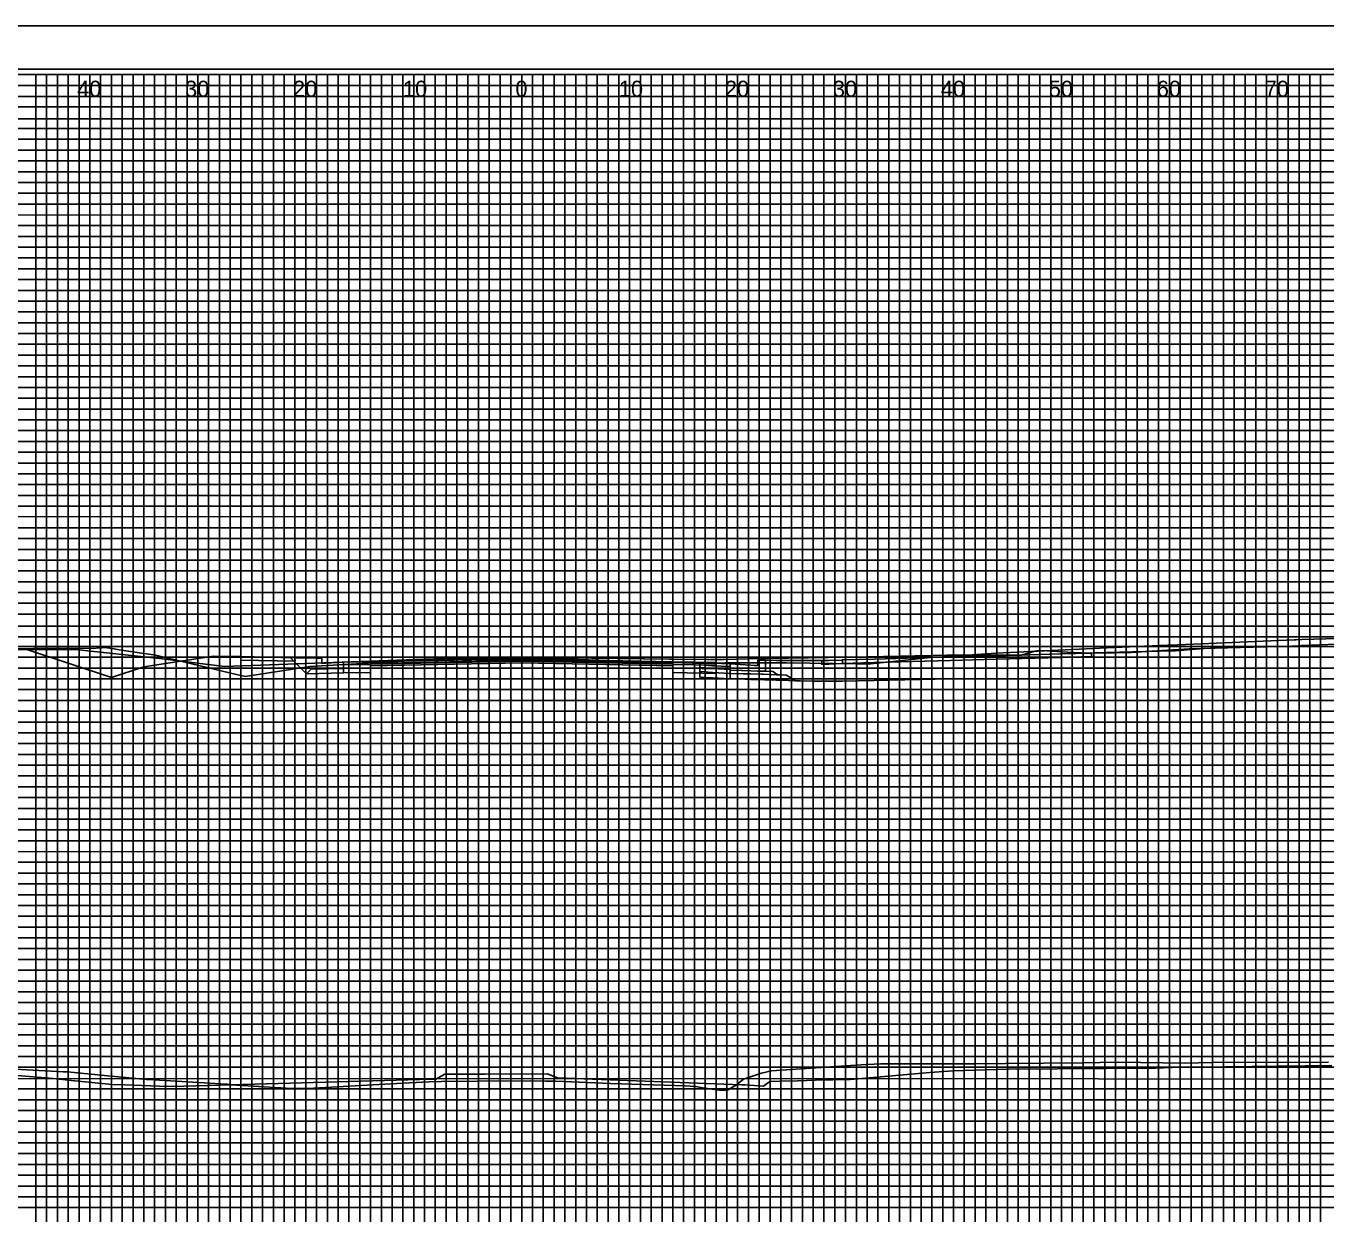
# Model space of a CAD drawing. Extents: x -13 to 760, y -5 to 1491.
# Drawn here: x 114.1 to 234.5, y 104.5 to 214.5 of the extents above; entities that cross this region are included whole.
import ezdxf

# ---------------------------------------------------------------- set-up
doc = ezdxf.new("R2010")
doc.units = 0
for name, color, linetype in [('Exist XS Ground Line', 7, 'Continuous'), ('Prop CMT Concrete Structures', 7, 'Continuous'), ('Prop CMT Pvmt Course 1', 7, 'Continuous'), ('Prop CMT Pvmt Course 2', 7, 'Continuous'), ('Prop CMT Pvmt Course 3', 7, 'Continuous'), ('Prop CMT Pvmt Course 4', 7, 'Continuous'), ('Prop CMT Subgrade Earthwork', 7, 'Continuous'), ('Prop Conc 4in Sidewalk', 7, 'Continuous'), ('Prop Conc Curb and Gutter', 7, 'Continuous'), ('Prop Conc Island Cover', 7, 'Continuous'), ('Prop Corridor Mesh Bottom', 7, 'Continuous'), ('Prop XS Finish Grade', 7, 'Continuous'), ('Prop XS Offset Labels', 7, 'Continuous'), ('Scratch_Level_9', 7, 'Continuous'), ('Sheet Cross Section CELL', 7, 'Continuous'), ('Sheet Cross Section Grid Major CELL', 7, 'Continuous'), ('Sheet Cross Section Grid Middle CELL', 7, 'Continuous'), ('Sheet Cross Section Grid Minor 1 CELL', 7, 'Continuous'), ('Sheet Cross Section Grid Minor 2 CELL', 7, 'Continuous'), ('Sheet Cutting Line CELL', 7, 'Continuous'), ('Sheet DOT Grid CELL', 7, 'Continuous'), ('Sheet Plot Border Inside CELL', 7, 'Continuous'), ('Sheet Plot Border Outside CELL', 7, 'Continuous')]:
    doc.layers.add(name, color=color, linetype=linetype)

msp = doc.modelspace()

# ---------------------------------------------------------------- linework, layer by layer
at = {"layer": 'Exist XS Ground Line'}
for points in [[(110.13, 156.74), (117.11, 156.83), (120.08, 156.81), (121.12, 156.87), (121.36, 156.89), (122.11, 156.8), (122.71, 156.7), (124.6, 156.41), (126.1, 156.21), (126.74, 156.03), (133.58, 154.41), (134.4, 154.22), (134.6, 154.24), (140.39, 155.14), (145.24, 155.43), (152.31, 155.83), (154.97, 155.85), (159.26, 155.88), (162.07, 155.87), (163.31, 155.86), (175.86, 155.44), (176.49, 155.43), (178.86, 155.47), (181.55, 155.48), (183.55, 155.48), (183.67, 155.48), (184.54, 155.48), (191.02, 155.4), (191.7, 155.4), (192.33, 155.38), (197.88, 155.99), (199.1, 156.05), (203.92, 156.37), (205.24, 156.43), (209.69, 156.66), (214.87, 156.9), (219.81, 157.11), (220.77, 157.16), (223.65, 157.28), (231.56, 157.62), (231.71, 157.63), (232.26, 157.65), (236.71, 157.76)], [(110.19, 156.72), (118.68, 156.73), (126.74, 155.85), (132.46, 155.16), (141.67, 155.47), (156.96, 156.05), (173.65, 155.83), (177.15, 155.78), (178.75, 155.79), (181.05, 155.84), (192.07, 156.04), (199.39, 156.18), (200.15, 156.19), (202.22, 156.22), (204.83, 156.19), (206.27, 156.2), (207.56, 156.56), (207.73, 156.61), (207.8, 156.61), (208.16, 156.62), (210.56, 156.47), (212.44, 156.39), (214.88, 156.41), (216.45, 156.43), (219.81, 156.65), (221.84, 156.78), (231.34, 157.04), (232.12, 157.07), (232.22, 157.08), (237.15, 157.28)], [(102.5, 118.14), (116.61, 116.96), (118.3, 116.77), (122.07, 116.4), (123.23, 116.38), (126.41, 116.24), (127.63, 116.22), (151.66, 116.89), (151.75, 116.89), (151.8, 116.89), (152.03, 116.9), (152.04, 116.9), (152.89, 117.36), (156.61, 117.37), (162.38, 117.41), (162.91, 117.18), (163.31, 117.02), (178.72, 116.45), (180.38, 116.38), (180.67, 116.37), (182.4, 116.26), (182.76, 116.52), (183, 116.69), (183.91, 116.72), (185.57, 116.76), (187.18, 116.8), (190.47, 116.88), (197.82, 117.52), (199.97, 117.68), (205.1, 117.83), (218.7, 117.93), (220.25, 117.98), (235.05, 118.16)], [(109.66, 118), (117.54, 117.59), (117.63, 117.58), (117.71, 117.58), (117.84, 117.58), (117.87, 117.58), (117.92, 117.57), (121.68, 117.21), (125.24, 116.88), (125.26, 116.88), (125.31, 116.88), (125.35, 116.87), (125.4, 116.86), (132.65, 116.44), (132.71, 116.43), (132.82, 116.41), (132.91, 116.4), (133, 116.39), (133.08, 116.39), (138.72, 116.05), (138.8, 116.05), (138.88, 116.04), (138.9, 116.04), (138.97, 116.04), (139.02, 116.03), (139.06, 116.03), (139.1, 116.03), (139.13, 116.03), (139.15, 116.03), (139.17, 116.04), (140.71, 116.08), (148.45, 116.49), (151.41, 116.65), (152.58, 116.7), (155.9, 116.72), (160.81, 116.74), (162.25, 116.73), (163.16, 116.71), (168.23, 116.51), (174.2, 116.31), (175.1, 116.28), (176.1, 116.23), (176.77, 116.1), (178.31, 115.88), (178.66, 115.88), (179.06, 115.88), (179.89, 116.39), (180.54, 116.9), (182.22, 117.45), (183.15, 117.68), (189.56, 118.1), (191.92, 118.25), (192.66, 118.29), (193.28, 118.32), (193.58, 118.33), (194.23, 118.32), (202.03, 118.31), (204.82, 118.37), (211.91, 118.42), (215.26, 118.48), (221.45, 118.4), (223.93, 118.44), (234.73, 118.47)]]:
    msp.add_lwpolyline(points, dxfattribs=at)
at = {"layer": 'Prop CMT Pvmt Course 1'}
for points in [[(143.5, 155.54), (146, 155.59), (146, 155.34), (146, 155.34), (143.5, 155.29), (143.5, 155.29), (143.5, 155.29), (143.5, 155.54), (143.5, 155.54)], [(146, 155.43), (146, 155.43), (146, 155.43), (160, 155.71), (174, 155.43), (174, 155.43), (174, 155.43), (174, 155.59), (174, 155.59), (160, 155.87), (146, 155.59), (146, 155.59), (146, 155.43)], [(178, 155.51), (174, 155.59), (174, 155.34), (174, 155.34), (178, 155.26), (178, 155.26), (178, 155.26), (178, 155.51), (178, 155.51)], [(176.5, 155.54), (176.5, 155.29), (177.68, 155.21), (179.3, 155.13), (179.3, 155.38), (177.68, 155.46), (176.5, 155.54)]]:
    msp.add_lwpolyline(points, dxfattribs=at)
at = {"layer": 'Prop CMT Pvmt Course 2'}
for points in [[(143.5, 155.29), (146, 155.34), (146, 155.01), (146, 155.01), (143.5, 154.96), (143.5, 154.96), (143.5, 154.96), (143.5, 155.29), (143.5, 155.29)], [(146, 155.37), (146, 155.37), (146, 155.37), (160, 155.65), (174, 155.37), (174, 155.37), (174, 155.37), (174, 155.43), (174, 155.43), (160, 155.71), (146, 155.43), (146, 155.43), (146, 155.37)], [(178, 155.26), (174, 155.34), (174, 155.01), (174, 155.01), (178, 154.93), (178, 154.93), (178, 154.93), (178, 155.26), (178, 155.26)], [(176.5, 155.29), (176.5, 155.04), (177.68, 154.96), (179.3, 154.88), (179.3, 155.13), (177.68, 155.21), (176.5, 155.29)]]:
    msp.add_lwpolyline(points, dxfattribs=at)
at = {"layer": 'Prop CMT Pvmt Course 3'}
for points in [[(146, 155.2), (146, 155.2), (146, 155.2), (160, 155.48), (174, 155.2), (174, 155.2), (174, 155.2), (174, 155.37), (174, 155.37), (160, 155.65), (146, 155.37), (146, 155.37), (146, 155.2)], [(143.5, 154.96), (143.5, 154.55), (140.07, 154.48), (140.5, 154.9), (143.5, 154.96)], [(143.5, 154.96), (146, 155.01), (146, 154.59), (146, 154.59), (143.5, 154.55), (143.5, 154.55), (143.5, 154.55), (143.5, 154.96), (143.5, 154.96)], [(178, 154.93), (174, 155.01), (174, 154.59), (174, 154.59), (178, 154.51), (178, 154.51), (178, 154.51), (178, 154.93), (178, 154.93)], [(176.5, 155.04), (176.5, 154.67), (177.68, 154.59), (179.3, 154.5), (179.3, 154.88), (177.68, 154.96), (176.5, 155.04)], [(183.68, 154.39), (183.7, 154.38), (183.64, 154.38), (183.61, 154.38), (182.2, 154.42), (181.21, 154.45), (180.51, 154.47), (179.3, 154.5), (179.3, 154.61), (179.3, 154.79), (180.46, 154.76), (181.21, 154.74), (182.08, 154.72), (183.27, 154.68), (183.33, 154.64), (183.61, 154.43), (183.68, 154.39)]]:
    msp.add_lwpolyline(points, dxfattribs=at)
at = {"layer": 'Prop CMT Pvmt Course 4'}
for points in [[(176.5, 154.67), (176.5, 154.17), (177.68, 154.09), (179.3, 154), (179.3, 154.5), (177.68, 154.59), (176.5, 154.67)], [(183.88, 154.37), (184.51, 154.35), (184.83, 154.15), (185.34, 153.83), (184.09, 153.87), (183.61, 153.88), (182.52, 153.92), (181.21, 153.95), (180.66, 153.97), (179.3, 154), (179.3, 154.19), (179.3, 154.5), (180.59, 154.47), (181.21, 154.45), (182.37, 154.42), (183.61, 154.38), (183.88, 154.37)]]:
    msp.add_lwpolyline(points, dxfattribs=at)
at = {"layer": 'Prop CMT Subgrade Earthwork'}
for points in [[(140.07, 154.48), (138.57, 155.97)], [(143.5, 154.55), (140.07, 154.48)], [(143.5, 154.55), (143.5, 154.55), (146, 154.59)], [(178, 154.51), (178, 154.51), (174, 154.59)], [(185.34, 153.83), (184.09, 153.87), (183.61, 153.88), (182.52, 153.92), (181.21, 153.95), (180.66, 153.97), (179.3, 154)], [(185.34, 153.83), (185.48, 153.82), (185.5, 153.82), (185.79, 153.81), (185.8, 153.81), (186.91, 153.78), (187.07, 153.78), (187.51, 153.77), (187.6, 153.77), (187.78, 153.77), (188.45, 153.77), (188.8, 153.78), (189.7, 153.8)], [(189.7, 153.8), (192.64, 153.86), (199.71, 154), (201.39, 154.04)]]:
    msp.add_lwpolyline(points, dxfattribs=at)
at = {"layer": 'Prop Conc 4in Sidewalk'}
for points in [[(139, 155.96), (139.01, 155.63), (133.98, 155.73), (133.99, 156.06), (139, 155.96)], [(189.7, 155.71), (189.7, 155.41), (189.64, 155.41), (188.45, 155.37), (188.43, 155.37), (187.79, 155.36), (187.81, 155.62), (187.82, 155.7), (188.43, 155.71), (188.45, 155.71), (189.64, 155.74), (189.7, 155.75), (189.7, 155.71)], [(189.7, 155.75), (192.64, 155.83), (199.71, 156.03), (202.84, 156.11), (209.9, 156.31), (212.75, 156.39), (212.8, 156.06), (209.9, 155.98), (202.84, 155.78), (199.71, 155.69), (192.64, 155.5), (189.7, 155.41), (189.7, 155.75)]]:
    msp.add_lwpolyline(points, dxfattribs=at)
at = {"layer": 'Prop Conc Curb and Gutter'}
for points in [[(141.84, 155.44), (143.5, 155.54), (143.5, 154.96), (143.5, 154.96), (141.51, 154.92), (141, 154.91), (141, 155.17), (141, 155.92), (141.12, 155.92), (141.5, 155.92), (141.5, 155.53), (141.5, 155.42), (141.84, 155.44)], [(181.56, 155.24), (181.87, 155.23), (181.87, 155.35), (181.87, 155.73), (182.29, 155.72), (182.57, 155.72), (182.57, 155.24), (182.57, 154.7), (181.85, 154.72), (181.21, 154.74), (180.36, 154.77), (179.3, 154.79), (179.3, 155.01), (179.3, 155.38), (180.23, 155.32), (181.21, 155.26), (181.56, 155.24)]]:
    msp.add_lwpolyline(points, dxfattribs=at)
at = {"layer": 'Prop Conc Island Cover'}
msp.add_lwpolyline([(133.99, 156.06), (133.81, 156.06), (131.49, 156.11), (131.46, 156.1), (125, 155.12)], dxfattribs=at)
at = {"layer": 'Prop Corridor Mesh Bottom'}
for points in [[(122, 154.12), (114.17, 156.72)], [(156.96, 156.05), (146, 155.64), (146, 155.64), (146, 155.39), (146, 155.39), (146, 155.39), (156.96, 155.68), (156.96, 155.68), (160, 155.76), (160, 155.76), (160, 156.01), (156.96, 156.05), (156.96, 156.05)], [(173.65, 155.83), (160, 156.01), (160, 155.76), (160, 155.76), (173.65, 155.58), (173.65, 155.58), (174, 155.57), (174, 155.57), (174, 155.82), (173.65, 155.83), (173.65, 155.83)], [(125, 155.12), (122, 154.12)]]:
    msp.add_lwpolyline(points, dxfattribs=at)
at = {"layer": 'Prop XS Finish Grade'}
for points in [[(212.75, 156.39), (213.03, 156.4), (220.09, 156.6), (220.52, 156.61)], [(220.52, 156.61), (223.22, 156.8), (224.36, 156.88)], [(139, 155.96), (140.35, 155.94), (141, 155.92)], [(176.5, 155.54), (177.68, 155.46), (179.3, 155.38)], [(187.82, 155.7), (187.63, 155.69), (187.6, 155.69), (187.58, 155.69), (187.07, 155.69), (186.87, 155.69), (185.8, 155.7), (185.68, 155.7), (185.5, 155.7), (184.25, 155.71), (183.61, 155.71), (182.57, 155.72)]]:
    msp.add_lwpolyline(points, dxfattribs=at)
at = {"layer": 'Scratch_Level_9'}
msp.add_lwpolyline([(143.5, 155.54), (143.5, 155.29)], dxfattribs=at)
at = {"layer": 'Sheet Cross Section CELL'}
msp.add_lwpolyline([(320, 210), (0, 210), (0, 0), (320, 0)], close=True, dxfattribs=at)
at = {"layer": 'Sheet Cross Section Grid Major CELL'}
for p, q in [((130, 210), (120, 210)), ((120, 210), (120, 0)), ((130, 0), (130, 210)), ((150, 210), (140, 210)), ((140, 210), (140, 0)), ((150, 0), (150, 210)), ((170, 210), (160, 210)), ((160, 210), (160, 0)), ((170, 0), (170, 210)), ((190, 210), (180, 210)), ((180, 210), (180, 0)), ((190, 0), (190, 210)), ((210, 210), (200, 210)), ((200, 210), (200, 0)), ((210, 0), (210, 210)), ((230, 210), (220, 210)), ((220, 210), (220, 0)), ((230, 0), (230, 210))]:
    msp.add_line(p, q, dxfattribs=at)
for points in [[(0, 200), (320, 200), (320, 190), (0, 190)], [(0, 180), (320, 180), (320, 170), (0, 170)], [(0, 160), (320, 160), (320, 150), (0, 150)], [(0, 140), (320, 140), (320, 130), (0, 130)], [(0, 120), (320, 120), (320, 110), (0, 110)]]:
    msp.add_lwpolyline(points, dxfattribs=at)
at = {"layer": 'Sheet Cross Section Grid Middle CELL'}
for points in [[(115, 0), (115, 210), (125, 210), (125, 0)], [(135, 0), (135, 210), (145, 210), (145, 0)], [(155, 0), (155, 210), (165, 210), (165, 0)], [(175, 0), (175, 210), (185, 210), (185, 0)], [(195, 0), (195, 210), (205, 210), (205, 0)], [(215, 0), (215, 210), (225, 210), (225, 0)], [(0, 205), (275, 205)], [(0, 185), (320, 185), (320, 195), (0, 195)], [(0, 165), (320, 165), (320, 175), (0, 175)], [(0, 145), (320, 145), (320, 155), (0, 155)], [(0, 125), (320, 125), (320, 135), (0, 135)], [(0, 105), (320, 105), (320, 115), (0, 115)]]:
    msp.add_lwpolyline(points, dxfattribs=at)
at = {"layer": 'Sheet Cross Section Grid Minor 1 CELL'}
for p, q in [((0, 209), (260, 209)), ((260, 207.98), (0, 207.98)), ((0, 207), (260, 207)), ((260, 205.89), (0, 205.89)), ((0, 204), (320, 204))]:
    msp.add_line(p, q, dxfattribs=at)
for points in [[(0, 203), (270, 203), (320, 203), (320, 202), (0, 202)], [(0, 201), (320, 201), (320, 199), (0, 199)], [(0, 198), (320, 198), (320, 197), (0, 196.98)], [(0, 196), (320, 196), (320, 194), (0, 194)], [(0, 193), (320, 193), (320, 192), (0, 192)], [(0, 191), (320, 191), (320, 189), (0, 189)], [(0, 188), (320, 188), (320, 187), (0, 187)], [(0, 186), (320, 186), (320, 184), (0, 184)], [(0, 183), (320, 183), (320, 182), (0, 182)], [(0, 181), (320, 181), (320, 179), (0, 179)], [(0, 178), (320, 178), (320, 177), (0, 177)], [(0, 176), (320, 176), (320, 173.95), (320, 173), (320, 172), (0, 172)], [(0, 174), (320, 174), (320, 173), (0, 173)], [(0, 171), (320, 171), (320, 169), (0, 169.03)], [(0, 169.03), (320, 169), (320, 168), (0, 168)], [(0, 167), (320, 167), (320, 166), (0, 166)], [(0, 164), (320, 164), (320, 163), (0, 163)], [(0, 162), (320, 162), (320, 161), (0, 161)], [(-0.07, 158.89), (320, 158.89), (320, 157.88), (-0.07, 157.88)], [(0, 157), (320, 157), (320, 156), (0, 156)], [(0, 154), (320, 154), (320, 153), (0, 153)], [(0, 152), (320, 152), (320, 151), (0, 151)], [(0, 149), (320, 149), (320, 148), (0, 148)], [(0, 147), (320, 147), (320, 146), (0, 146)], [(0, 144), (320, 144), (320, 143), (0, 143)], [(0, 142), (320, 142), (320, 141), (0, 141)], [(0, 139), (320, 139), (319.99, 137.98), (0, 138)], [(0, 137), (320, 137), (320, 136), (0, 136)], [(0, 134), (320, 134), (320, 133), (0, 133)], [(0, 132), (320, 132), (320, 131), (0, 131)], [(0, 129), (320, 129), (320, 128), (0, 128)], [(0, 127), (320, 127), (320, 126), (0, 126)], [(0, 124), (320, 124), (320, 123), (0, 123)], [(0, 122), (320, 122), (320, 121), (0, 121)], [(0, 119), (320, 119), (320, 118), (0, 118)], [(0, 116.99), (320.07, 116.91), (320, 116), (0, 116)], [(0, 114), (320, 114), (320, 113), (0, 113)], [(0, 112), (320, 112), (320, 111), (0, 111)], [(0, 109), (320, 109), (320, 108), (0, 108)], [(0, 107), (320, 107), (320, 106), (0, 106)]]:
    msp.add_lwpolyline(points, dxfattribs=at)
at = {"layer": 'Sheet Cross Section Grid Minor 2 CELL'}
for points in [[(115, 0), (116, 0), (116, 210), (117, 210), (117, 0)], [(117, 0), (118, 0), (118, 210), (119, 210), (119, 0)], [(120, 0), (121, 0), (121, 210), (122, 210), (122, 0)], [(122, 0), (123, 0), (123, 210), (124, 210), (124, 0)], [(125, 0), (126, 0), (126, 210), (127, 210), (127, 0)], [(127, 0), (128, 0), (128, 210), (129, 210), (129, 0)], [(130, 0), (131, 0), (131, 210), (132, 210), (132, 0)], [(132, 0), (133, 0), (133, 210), (134, 210), (134, 0)], [(135, 0), (136, 0), (136, 210), (137, 210), (137, 0)], [(137, 0), (138, 0), (138, 210), (139, 210), (139, 0)], [(140, 0), (141, 0), (141, 210), (142, 210), (142, 0)], [(142, 0), (143, 0), (143, 210), (144, 210), (144, 0)], [(145, 0), (146, 0), (146, 210), (147, 210), (147, 0)], [(147, 0), (148, 0), (148, 210), (149, 210), (149, 0)], [(150, 0), (151, 0), (151, 210), (152, 210), (152, 0)], [(152, 0), (153, 0), (153, 210), (154, 210), (154, 0)], [(155, 0), (156, 0), (156, 210), (157, 210), (157, 0)], [(157, 0), (158, 0), (158, 210), (159, 210), (159, 0)], [(160, 0), (161, 0), (161, 210), (162, 210), (162, 0)], [(162, 0), (163, 0), (163, 210), (164, 210), (164, 0)], [(165, 0), (166, 0), (166, 210), (167, 210), (167, 0)], [(167, 0), (168, 0), (168, 210), (169, 210), (169, 0)], [(170, 0), (171, 0), (171, 210), (172, 210), (172, 0)], [(172, 0), (173, 0), (173, 210), (174, 210), (174, 0)], [(175, 0), (176, 0), (176, 210), (177, 210), (177, 0)], [(177, 0), (178, 0), (178, 210), (179, 210), (179, 0)], [(180, 0), (181, 0), (181, 210), (182, 210), (182, 0)], [(182, 0), (183, 0), (183, 210), (184, 210), (184, 0)], [(185, 0), (186, 0), (186, 210), (187, 210), (187, 0)], [(187, 0), (188, 0), (188, 210), (189, 210), (189, 0)], [(190, 0), (191, 0), (191, 210), (192, 210), (192, 0)], [(192, 0), (193, 0), (193, 210), (194, 210), (194, 0)], [(195, 0), (196, 0), (196, 210), (197, 210), (197, 0)], [(197, 0), (198, 0), (198, 210), (199, 210), (199, 0)], [(200, 0), (201, 0), (201, 210), (202, 210), (202, 0)], [(202, 0), (203, 0), (203, 210), (204, 210), (204, 0)], [(205, 0), (206, 0), (206, 210), (207, 210), (207, 0)], [(207, 0), (208, 0), (208, 210), (209, 210), (209, 0)], [(210, 0), (211, 0), (211, 210), (212, 210), (212, 0)], [(212, 0), (213, 0), (213, 210), (214, 210), (214, 0)], [(215, 0), (216, 0), (216, 210), (217, 210), (217, 0)], [(217, 0), (218, 0), (218, 210), (219, 210), (219, 0)], [(220, 0), (221, 0), (221, 210), (222, 210), (222, 0)], [(222, 0), (223, 0), (223, 210), (224, 210), (224, 0)], [(225, 0), (226, 0), (226, 210), (227, 210), (227, 0)], [(227, 0), (228, 0), (228, 210), (229, 210), (229, 0)], [(230, 0), (231, 0), (231, 210), (232, 210), (232, 0)], [(232, 0), (233, 0), (233, 210), (234, 210), (234, 0)]]:
    msp.add_lwpolyline(points, dxfattribs=at)
at = {"layer": 'Sheet Cutting Line CELL'}
msp.add_line((323.3, 214.5), (-13.4, 214.5), dxfattribs=at)
at = {"layer": 'Sheet DOT Grid CELL'}
for p, q in [((120, 0), (120, 210)), ((130, 0), (130, 210)), ((140, 0), (140, 210)), ((150, 0), (150, 210)), ((160, 0), (160, 210)), ((170, 0), (170, 210)), ((180, 0), (180, 210)), ((190, 0), (190, 210)), ((200, 0), (200, 210)), ((210, 0), (210, 210)), ((220, 0), (220, 210)), ((230, 0), (230, 210)), ((0, 200), (320, 200)), ((0, 190), (320, 190)), ((0, 180), (320, 180)), ((0, 170), (320, 170)), ((0, 160), (320, 160)), ((0, 150), (320, 150)), ((0, 140), (320, 140)), ((0, 130), (320, 130)), ((0, 120), (320, 120)), ((0, 110), (320, 110))]:
    msp.add_line(p, q, dxfattribs=at)
at = {"layer": 'Sheet Plot Border Inside CELL'}
msp.add_lwpolyline([(-10.8, -0.5), (322.4, -0.5), (322.4, 210.5), (-10.8, 210.5)], close=True, dxfattribs=at)
at = {"layer": 'Sheet Plot Border Outside CELL'}
msp.add_lwpolyline([(-13.4, -4.5), (323.3, -4.5), (323.3, 214.5), (-13.4, 214.5)], close=True, dxfattribs=at)

# ---------------------------------------------------------------- texts
at = {"layer": 'Prop CMT Concrete Structures'}
for p in [(176.5, 155.54), (179.3, 155.38), (181.87, 155.22)]:
    msp.add_text('X', height=0.0025, dxfattribs=at).set_placement(p)
at = {"layer": 'Prop XS Offset Labels'}
for s, p in [('40', (118.83, 207.93)), ('30', (128.83, 207.93)), ('20', (138.83, 207.93)), ('10', (149.01, 207.93)), ('0', (159.42, 207.93)), ('0', (159.42, 207.93)), ('10', (169.01, 207.93)), ('20', (178.83, 207.93)), ('30', (188.83, 207.93)), ('40', (198.83, 207.93)), ('50', (208.83, 207.93)), ('60', (218.83, 207.93)), ('70', (228.83, 207.93))]:
    msp.add_text(s, height=1.5, dxfattribs=at).set_placement(p)
at = {"layer": 'Scratch_Level_9'}
for p in [(114.17, 156.72), (133.99, 156.06), (138.99, 155.96), (141.5, 155.42), (143.5, 155.54), (143.5, 155.54), (160, 155.87), (178, 155.51)]:
    msp.add_text('X', height=0.0025, dxfattribs=at).set_placement(p)

doc.saveas('drawing.dxf')
